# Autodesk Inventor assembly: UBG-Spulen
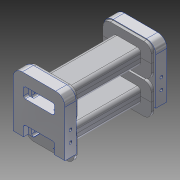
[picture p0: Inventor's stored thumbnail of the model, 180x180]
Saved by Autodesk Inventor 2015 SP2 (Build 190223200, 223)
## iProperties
Created: 2012-07
Part Number: UBG-Spulen
Document SubType Name: Assembly
Designer: rYan
Mass: 23.7366 g
Surface Area: 100.02 cm^2
Volume: 9.84279 cm^3
Density: 2.41157 g/cm^3
Author: rYan
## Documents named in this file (3)
- D:\TIGERs GIT\Hardware\mechanik\2016\Inventor\Kicker\UBG-Spulen.iam
- D:\TIGERs GIT\Hardware\mechanik\2016\Inventor\Kicker\Spulenhalter.ipt
- D:\TIGERs GIT\Hardware\mechanik\2016\Inventor\Kicker\MG-Spulenkoerper.iam
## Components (4 placed, 2 different names)
1. Spulenhalter:1 — Passend:1, Passend:2, Fluchtend:3, Fluchtend:4, Fluchtend:5, Fluchtend:6
2. Spulenhalter:2 — Fluchtend:5, Fluchtend:6, Passend:3, Passend:4, Passend:5
3. MG-Spulenkoerper:1 [sub-assembly] — Passend:1, Fluchtend:3, Passend:3, Passend:4
4. MG-Spulenkoerper:2 [sub-assembly] — Passend:2, Fluchtend:4, Passend:5
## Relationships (9: Mate 5, Flush 4)
- Passend:1 [Mate]: Spulenhalter:1 ↔ MG-Spulenkoerper:1
- Passend:2 [Mate]: Spulenhalter:1 ↔ MG-Spulenkoerper:2
- Fluchtend:3 [Flush]: Spulenhalter:1 ↔ MG-Spulenkoerper:1
- Fluchtend:4 [Flush]: Spulenhalter:1 ↔ MG-Spulenkoerper:2
- Fluchtend:5 [Flush]: Spulenhalter:1 ↔ Spulenhalter:2
- Fluchtend:6 [Flush]: Spulenhalter:1 ↔ Spulenhalter:2
- Passend:3 [Mate]: Spulenhalter:2 ↔ MG-Spulenkoerper:1
- Passend:4 [Mate]: Spulenhalter:2 ↔ MG-Spulenkoerper:1
- Passend:5 [Mate]: Spulenhalter:2 ↔ MG-Spulenkoerper:2
